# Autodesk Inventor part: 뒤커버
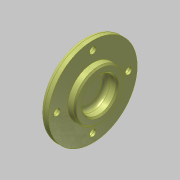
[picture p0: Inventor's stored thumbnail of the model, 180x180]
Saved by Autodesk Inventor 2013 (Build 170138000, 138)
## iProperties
Created: 2015-12
Part Number: 뒤커버
Document SubType Name: Modeling
Designer: mdu
Density: 2.71 g/cm^3
Material: 알루미늄 6061
Mass: 56.199 g
Surface Area: 84.0424 cm^2
Volume: 20.7376 cm^3
Author: mdu
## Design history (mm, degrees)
sketch "스케치1"
  geometry: L1 (-7, 0)-(7, 0); L2 (-7, 0)-(-7, 15.539); L3 (-7, 15.539)-(-4, 18.5); L4 (-4, 18.5)-(-4, 31); L5 (-4, 31)-(2, 31); L6 (2, 31)-(2, 17.5); L7 (2, 17.5)-(7, 17.5); L8 (7, 17.5)-(7, 0); 2 further points
  constraints: 16 end point, 4 parallel, 2 perpendicular, 1 coincident, 1 horizontal, 1 midpoint
  dimensions: "d0" = 14 distance of L1.start L1.end; "d1" = 62 diameter of L5 L1; "d2" = 35 diameter of L7 L1; "d3" = 37 diameter of L3.end L1; "d4" = 3 distance between parallel lines of L4 L2; "d5" = 6 distance of L4.end L5.end
revolve "회전1" sketch "스케치1" stored, may be unused: angle "d6" = 90 deg
sketch "스케치2" dims "d32" = 50
  geometry: 3 further points
  constraints: 2 vertical alignment, 1 coincident, 2 other
hole "구멍1" sketch "스케치2" at (0, 25) diameter "d8" = 4.5; stored, may be unused: countersink angle "d12" = 90 deg, drill point angle "d14" = 118 deg; dims "d9" = 6, "d10" = 8, "d11" = 4.4, "d13" = 8
hole "구멍2" diameter "d20" = 24; stored, may be unused: countersink angle "d24" = 90 deg, drill point angle "d26" = 0 deg; dims "d18" = 10, "d19" = 10, "d21" = 6, "d22" = 8, "d23" = 4.4, "d25" = 8
fillet "모깎기1" dims "d27" = 3
fillet "모깎기2" dims "d28" = 3
chamfer "모따기1" distance "d29" = 1; stored, may be unused: second distance "d30" = 2, angle "d31" = 45 deg
node "솔리드1"
pattern_circular "원형 패턴1" dims angle "d16" = 360 deg
